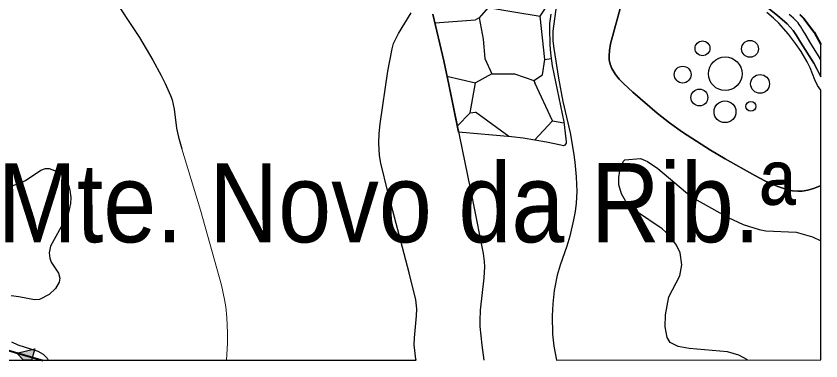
# Model space of a CAD drawing. Extents: x -64005 to -55000, y -89025 to -80000.
# Drawn here: x -55813 to -55000, y -89000 to -88651 of the extents above; entities that cross this region are included whole.
import ezdxf
from ezdxf.enums import TextEntityAlignment as Align

# ---------------------------------------------------------------- set-up
doc = ezdxf.new("R2010")
doc.units = 0
doc.header["$LTSCALE"] = 32
doc.linetypes.add('DASH_DOUBLE_DOT', pattern=[9.2, 5, -1.2, 0.3, -1.2, 0.3, -1.2])
doc.linetypes.add('DOT_DASHED', pattern=[7.7, 5, -1.2, 0.3, -1.2])
for name, color, linetype, lineweight in [('1', 7, 'Continuous', 25), ('18', 7, 'Continuous', 25), ('19', 7, 'Continuous', 25), ('2', 7, 'Continuous', 25), ('24', 7, 'Continuous', 25), ('3', 7, 'Continuous', 25), ('34', 7, 'Continuous', 25), ('53', 7, 'DASH_DOUBLE_DOT', 25)]:
    doc.layers.add(name, color=color, linetype=linetype, lineweight=lineweight)
doc.layers.add('45', color=7, linetype='Continuous')

msp = doc.modelspace()

# ---------------------------------------------------------------- hatches: boundary and pattern name
at = {"layer": '18'}
msp.add_hatch(color=256, dxfattribs=at).paths.add_polyline_path([(-55797.34, -88999.14), (-55805.4, -88999.14), (-55811.99, -88992.2), (-55794.01, -88987.87)])

# ---------------------------------------------------------------- linework, layer by layer
at = {"layer": '1'}
for points in [[(-55074.21, -88999.07), (-55082.9, -88994.26), (-55094.19, -88990.82), (-55133.15, -88987.55), (-55144.22, -88985.38), (-55152.24, -88981.45), (-55155.39, -88976.19), (-55157.17, -88965.51), (-55156.96, -88953.55), (-55153.45, -88935.18), (-55142.48, -88913.88), (-55140.59, -88902.85), (-55142.22, -88890.8), (-55145.71, -88883.09), (-55152.81, -88873.38), (-55160.39, -88866.5), (-55186.12, -88849.05), (-55197.23, -88838.17), (-55201.53, -88831.24), (-55204.11, -88821.9), (-55204.13, -88814.42), (-55203.16, -88807.82), (-55199.48, -88798.06), (-55197.94, -88796.8), (-55182.24, -88795.26), (-55175.2, -88798.39), (-55164.72, -88805.54), (-55130.36, -88834.36), (-55093.72, -88854.95), (-55078.39, -88862.03), (-55062.3, -88867.3), (-55055.64, -88868.39), (-55024.95, -88869.87), (-55008.5, -88874.45), (-55000.02, -88878.7)], [(-55821.83, -88824.68), (-55808.97, -88820.37), (-55803.37, -88817.67), (-55787.81, -88807.15), (-55783.21, -88805.47), (-55779.52, -88805.64), (-55771.41, -88808.58), (-55767.66, -88811.37), (-55763.29, -88816.29), (-55760.01, -88822.21), (-55758.4, -88827.41), (-55757.51, -88834.95), (-55757.88, -88840.96), (-55759.96, -88849.82), (-55763.43, -88857.7), (-55778.21, -88883.86), (-55779.38, -88890.68), (-55778.86, -88896.11), (-55777.33, -88900.08), (-55769.99, -88911.35), (-55768.6, -88916.39), (-55769.22, -88920.35), (-55773.07, -88926.65), (-55779.44, -88932.97), (-55789.09, -88937.86), (-55794.26, -88938.31), (-55810.08, -88935.06), (-55817.85, -88934.23)], [(-55817.44, -88980.71), (-55811.09, -88983.66), (-55790.91, -88990.06), (-55785.56, -88993.26), (-55781.57, -88997.27), (-55780.28, -88999.14)]]:
    msp.add_lwpolyline(points, dxfattribs=at)
at = {"layer": '18'}
msp.add_line((-55788.52, -88999.14), (-55796.63, -88996.74), dxfattribs=at)
at = {"layer": '18', "linetype": 'DOT_DASHED', "lineweight": 40}
msp.add_lwpolyline([(-55785.61, -89000), (-55892.77, -88968.32), (-56019.51, -88930.17), (-56280.02, -88850.32), (-56575.76, -88760.83), (-56782.32, -88697.86), (-56995.51, -88708.52), (-57161.56, -88661.81), (-59155.46, -88790.04)], dxfattribs=at)
at = {"layer": '18'}
msp.add_lwpolyline([(-55797.34, -88999.14), (-55805.4, -88999.14), (-55811.99, -88992.2), (-55794.01, -88987.87)], close=True, dxfattribs=at)
at = {"layer": '19'}
for p, q in [((-55389.82, -88658.28), (-55348.89, -88655.08)), ((-55278.98, -88695.28), (-55272.51, -88694.28)), ((-55377.63, -88712.32), (-55348.89, -88718.73)), ((-55354.24, -88749.23), (-55348.89, -88748.43)), ((-55315.24, -88773.19), (-55348.89, -88748.43)), ((-55271.02, -88757.24), (-55259.64, -88759.18))]:
    msp.add_line(p, q, dxfattribs=at)
for points in [[(-55336.04, -88642.63), (-55310, -88647.06), (-55283.41, -88651.5), (-55265.31, -88623.72), (-55277.66, -88581.42), (-55290.43, -88573.5)], [(-55343.71, -88613.59), (-55336.04, -88642.63), (-55345.02, -88653.24), (-55348.89, -88655.08)], [(-55365.97, -88768.61), (-55375.88, -88720.46), (-55380.97, -88696.75), (-55391.84, -88649.47)], [(-55272.9, -88649.62), (-55273.97, -88658.95), (-55274.12, -88663.66), (-55273.8, -88680.57), (-55273.21, -88689.02), (-55271.54, -88701.61), (-55259.75, -88758.34), (-55257.54, -88775.65), (-55257.25, -88778.46), (-55257.42, -88779.86), (-55258.65, -88781.91), (-55259.97, -88782.54), (-55262.7, -88781.91), (-55277.06, -88778.96), (-55300.59, -88774.91), (-55312.42, -88773.44), (-55365.97, -88768.61)], [(-55345.02, -88653.24), (-55341.03, -88674.78), (-55339.3, -88694.41), (-55332.26, -88709.83), (-55348.89, -88718.73)], [(-55289.98, -88716.43), (-55281.17, -88710.7), (-55278.98, -88695.28), (-55283.41, -88651.5)], [(-55332.26, -88709.83), (-55309.36, -88709.83), (-55289.98, -88716.43), (-55288.91, -88718.73)], [(-55367.22, -88762.53), (-55354.24, -88749.23), (-55348.89, -88718.73)], [(-55289.14, -88776.88), (-55271.02, -88757.24), (-55288.91, -88718.73)]]:
    msp.add_lwpolyline(points, dxfattribs=at)
at = {"layer": '2'}
for points in [[(-55790.07, -88425.95), (-55793.27, -88474.49), (-55793.39, -88479.69), (-55792.41, -88490.01), (-55790.07, -88500.22), (-55787.94, -88506.96), (-55782.72, -88520.28), (-55771.82, -88543.63), (-55765.85, -88554.79), (-55756.05, -88571.12), (-55717.31, -88628.49), (-55688.34, -88673.06), (-55674.73, -88695.85), (-55666.35, -88711.47), (-55662.42, -88719.45), (-55656.93, -88731.67), (-55655.3, -88736.19), (-55653.23, -88745.52), (-55650.87, -88764.61), (-55648.87, -88773.95), (-55645.39, -88785.46)], [(-55391.84, -88649.47), (-55380.98, -88696.75), (-55375.88, -88720.46), (-55351.52, -88839), (-55341.02, -88891.51), (-55339.98, -88899.59), (-55339.78, -88905), (-55340.27, -88915.88), (-55344.21, -88948.7), (-55344.63, -88959.61), (-55344.38, -88965.04), (-55342.35, -88984.09), (-55340.49, -88999.1)]]:
    msp.add_lwpolyline(points, dxfattribs=at)
at = {"layer": '2', "lineweight": 13}
msp.add_lwpolyline([(-55645.39, -88785.46), (-55626.54, -88847.75), (-55612.35, -88898.19), (-55605.53, -88923.55), (-55602.31, -88937.95), (-55601.13, -88945.22), (-55599.9, -88956.19), (-55599.23, -88971.69), (-55599.36, -88982.05), (-55600.43, -88999.12)], dxfattribs=at)
at = {"layer": '24'}
for points in [[(-55193.04, -88608.62), (-55200.66, -88636.29), (-55212.37, -88679.51), (-55213.54, -88686.07), (-55213.86, -88691.61), (-55213.73, -88695.78), (-55212.89, -88700), (-55211.16, -88704.46), (-55207.56, -88710.36), (-55203.67, -88715.13), (-55199.3, -88719.66), (-55190.03, -88728.18), (-55165.37, -88749.43)], [(-55213.54, -88686.07), (-55212.37, -88679.51), (-55200.66, -88636.29), (-55193.04, -88608.62), (-55192.76, -88607.9)], [(-55266.96, -88639.47), (-55270.75, -88666.81), (-55270.71, -88676.43), (-55269.82, -88684.12), (-55265, -88714.09), (-55260.54, -88737.93), (-55253.39, -88769.53), (-55249.83, -88789.22), (-55248.47, -88799.13), (-55247.08, -88814.02), (-55246.62, -88828.88), (-55247.07, -88840.5), (-55248.15, -88848.93), (-55249.75, -88857.33), (-55253.71, -88874.06), (-55256.59, -88883.96), (-55263.47, -88903.37), (-55266.43, -88913.17), (-55269.38, -88928.78), (-55270.88, -88942.27), (-55271.49, -88954.52), (-55270.99, -88972.9), (-55269.7, -88985.06), (-55267.11, -88999.09), (-55000, -88999.06)], [(-55409.23, -88938.33), (-55415.67, -88910.91), (-55437.37, -88829.23), (-55444.43, -88800.04), (-55445.75, -88792.24), (-55446.45, -88779.96), (-55446.08, -88770.09), (-55445.11, -88760.18), (-55437.5, -88707.21), (-55433.16, -88684.56), (-55431.51, -88679.12), (-55429.73, -88674.95), (-55426.5, -88668.89), (-55413.9, -88648.24)], [(-55000.03, -88726.19), (-55003.35, -88721.56), (-55006.22, -88715.78), (-55010.93, -88703.6), (-55013.73, -88697.74), (-55020.07, -88687.22), (-55025.59, -88679.05), (-55032.69, -88669.62), (-55042.48, -88658.57), (-55047.74, -88653.52), (-55054.71, -88647.76)], [(-55043.49, -88823.53), (-55055.83, -88818.29), (-55066.75, -88812.72), (-55096.78, -88795.7), (-55111.4, -88786.96), (-55139.82, -88768.69), (-55152.8, -88759.3), (-55165.37, -88749.43), (-55190.03, -88728.18), (-55199.3, -88719.66), (-55203.67, -88715.13), (-55207.56, -88710.36), (-55211.16, -88704.46), (-55212.89, -88700), (-55213.73, -88695.78), (-55213.86, -88691.61), (-55213.54, -88686.07)], [(-55033.56, -88826.93), (-55028.8, -88828.01), (-55023.3, -88828.47), (-55018.83, -88828.29), (-55013.2, -88827.42), (-55006.45, -88825.47), (-55002.38, -88823.79), (-55001.98, -88823.7), (-55000.02, -88822.64), (-55000.03, -88726.19)], [(-55165.37, -88749.43), (-55152.8, -88759.3), (-55139.82, -88768.69), (-55111.4, -88786.96), (-55096.78, -88795.7), (-55066.75, -88812.72), (-55055.83, -88818.29), (-55043.49, -88823.53), (-55033.56, -88826.93)], [(-55002.38, -88823.79), (-55006.45, -88825.47), (-55013.2, -88827.42), (-55018.83, -88828.29), (-55023.3, -88828.47), (-55028.8, -88828.01), (-55033.56, -88826.93), (-55043.49, -88823.53)], [(-55000, -88999.06), (-55000.02, -88822.64), (-55001.98, -88823.7), (-55002.38, -88823.79)], [(-56446.67, -88874.11), (-56305.88, -88990.2), (-56294.66, -88999.19), (-55408.9, -88999.1)], [(-55408.9, -88999.1), (-55409.09, -88998.2), (-55410.72, -88983.82), (-55410.58, -88976.53), (-55408.38, -88954.56), (-55408.21, -88947.3), (-55409.23, -88938.33)]]:
    msp.add_lwpolyline(points, dxfattribs=at)
at = {"layer": '3'}
for points in [[(-55000.12, -88712.48), (-55006.99, -88699.07), (-55020.59, -88677.75), (-55024.71, -88671.14), (-55027.97, -88665.94), (-55034.11, -88659.18), (-55043.67, -88650.94), (-55058.77, -88638.93), (-55065.84, -88634.27), (-55075.93, -88628.13), (-55101.09, -88615.91), (-55113.81, -88610.31), (-55170.52, -88584.11)], [(-55170.52, -88584.11), (-55113.81, -88610.31), (-55101.09, -88615.91), (-55075.93, -88628.13), (-55065.84, -88634.27), (-55058.77, -88638.93), (-55043.67, -88650.94), (-55034.11, -88659.18), (-55027.97, -88665.94), (-55024.71, -88671.14), (-55020.59, -88677.75), (-55006.99, -88699.07), (-55000.03, -88712.66), (-55000.03, -88680.44)], [(-55000.03, -88680.44), (-55006.81, -88667.69), (-55017.4, -88653.9), (-55021.41, -88649.67)]]:
    msp.add_lwpolyline(points, dxfattribs=at)
at = {"layer": '3', "lineweight": 40}
msp.add_lwpolyline([(-55021.41, -88649.67), (-55017.4, -88653.9), (-55006.81, -88667.69), (-55000.13, -88680.26)], dxfattribs=at)
at = {"layer": '34'}
for centre, radius in [((-55119.58, -88684.07), 7.5), ((-55071.58, -88684.54), 8.5), ((-55096.61, -88709.72), 17), ((-55139.6, -88710.58), 8.5), ((-55061.45, -88719.96), 9.5), ((-55122.72, -88733.77), 8.5), ((-55096.86, -88748.15), 11), ((-55070.73, -88742.67), 5)]:
    msp.add_circle(centre, radius, dxfattribs=at)
at = {"layer": '53'}
msp.add_lwpolyline([(-55000.03, -88695.67), (-55002.42, -88691.72), (-55010.04, -88679.16), (-55015.83, -88669.5), (-55018.8, -88664.71), (-55020.34, -88662.34), (-55021.93, -88659.99), (-55023.12, -88658.38), (-55024.32, -88656.95), (-55025.5, -88655.66), (-55026.64, -88654.49), (-55027.76, -88653.44), (-55029.93, -88651.54), (-55031.91, -88649.96)], dxfattribs=at)

# ---------------------------------------------------------------- texts
at = {"layer": '45', "width": 0.9}
msp.add_text('Mte. Novo da Rib.ª', height=80, rotation=0.007, dxfattribs=at).set_placement((-55428.54, -88880.1), align=Align.CENTER)

doc.saveas('drawing.dxf')
